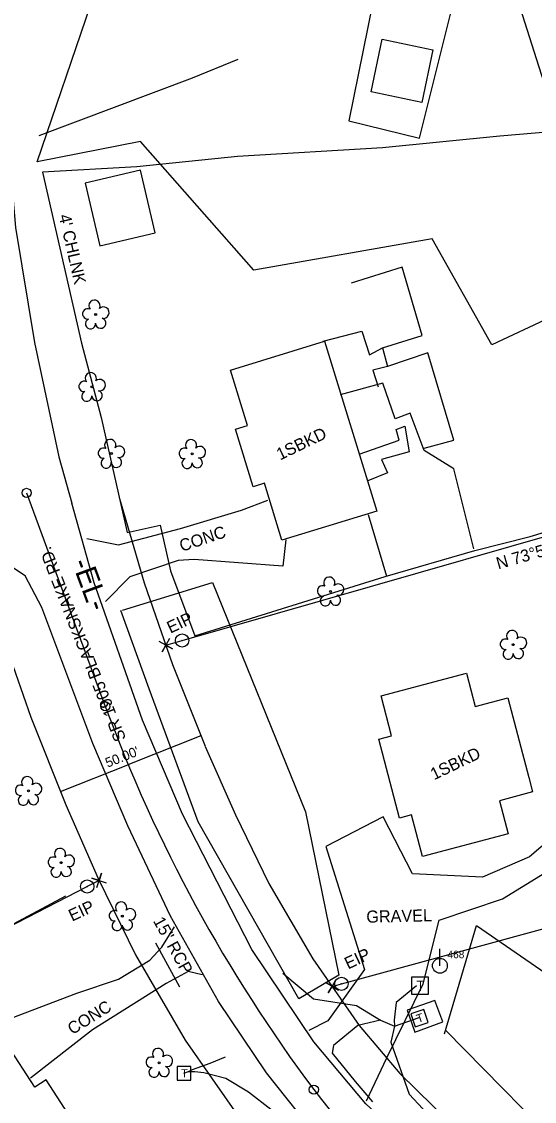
# Model space of a CAD drawing. Extents: x 1380524 to 1382335, y 594765 to 596944.
# Drawn here: x 1381171.1 to 1381340.7, y 595529.8 to 595887.1 of the extents above; entities that cross this region are included whole.
import ezdxf

# ---------------------------------------------------------------- set-up
doc = ezdxf.new("R2010")
doc.units = 0
for name, color, linetype in [('Exist Horizontal Alignment', 7, 'Continuous'), ('Exist Horizontal Alignment Direction Label', 7, 'Continuous'), ('Exist Horizontal Alignment Station Label', 7, 'Continuous'), ('Exist Other Culture Fence Line', 7, 'Continuous'), ('Exist Other Culture Fence Line Text', 7, 'Continuous'), ('Exist Roads EOP', 7, 'Continuous'), ('Exist Roads EOP Other', 7, 'Continuous'), ('Exist Structure Major Bridge WW', 7, 'Continuous'), ('Exist Structure Major Deck Tunnel Box Culvert', 7, 'Continuous'), ('Exist Structure Minor Pipes RCP 15 Inch', 7, 'Continuous'), ('Exist Structure Minor Pipes RCP 15 Inch Text', 7, 'Continuous'), ('Exist Utilities Power Tower CELL', 7, 'Continuous'), ('Exist Utilities Power Tower Text', 7, 'Continuous'), ('Exist Utilities Telephone Pedestal CELL', 7, 'Continuous'), ('Exist Utilities Telephone UG Cable', 7, 'Continuous'), ('Exist Vegetation Tree CELL', 7, 'Continuous'), ('Exist Vertical Profile Vertical Axis Label', 7, 'Continuous'), ('Prop Approach Slab', 7, 'Continuous'), ('Prop Approach Slab Hatching', 7, 'Continuous'), ('Prop Drainage Ditch Base Lines', 7, 'Continuous'), ('Prop Drainage Structure Pipe Elbow CELL', 7, 'Continuous'), ('Prop Drainage Structure Plot Symbol 50 Scale CELL', 7, 'Continuous'), ('Prop Earthen Structure Cut Ditch Special Detail Label', 7, 'Continuous'), ('Prop Earthen Structure Ditch Flow Line', 7, 'Continuous'), ('Prop Earthen Structure V Ditch Lateral Detail Label', 7, 'Continuous'), ('Prop Erosion Rip Rap At Embankment Detail CELL', 7, 'Continuous'), ('Prop Horizontal Alignment Tick Large', 7, 'Continuous'), ('Prop SS Transition Line', 7, 'Continuous')]:
    doc.layers.add(name, color=color, linetype=linetype)

# ---------------------------------------------------------------- blocks, each defined once
blk = doc.blocks.new('EXIST VEGETATION TREE')
at = {"layer": 'Prop Erosion Rip Rap At Embankment Detail CELL'}
blk.add_line((0, 0), (0, 0), dxfattribs=at)
blk.add_circle((0, 0), 0.00652, dxfattribs=at)
for centre, radius, start, end in [((-0.0077, 0.0575), 0.0371, 330.16508, 219.71335), ((-0.0521, 0.0031), 0.0345, 62.66361, 279.3457), ((0.051, 0.0118), 0.038, 257.1011, 134.19993), ((-0.0341, -0.0624), 0.0338, 111.56708, 6.23104), ((0.0335, -0.058), 0.034, 181.28216, 74.55999)]:
    blk.add_arc(centre, radius, start, end, dxfattribs=at)
blk = doc.blocks.new('EXIST UTILITIES POWER POLE')
at = {"layer": 'Exist Other Culture Fence Line'}
for q in [(0, 0.1125), (0, 0)]:
    blk.add_line((0, 0), q, dxfattribs=at)
blk.add_circle((0, 0), 0.049, dxfattribs=at)
blk = doc.blocks.new('EXIST UTILITIES TELEPHONE PEDESTAL')
at = {"layer": 'Exist Utilities Telephone Pedestal CELL'}
blk.add_line((0, 0), (0, 0), dxfattribs=at)
blk.add_lwpolyline([(-0.0545, -0.0565), (0.0574, -0.0565), (0.0574, 0.0554), (-0.0545, 0.0554), (-0.0545, -0.0565)], dxfattribs=at)
blk.add_text('T', height=0.0684, dxfattribs=at).set_placement((-0.0226, -0.0343))

msp = doc.modelspace()

# ---------------------------------------------------------------- linework, layer by layer
at = {"layer": 'Exist Horizontal Alignment'}
msp.add_line((1381172.77, 595731.19), (1381198.81, 595660.55), dxfattribs=at)
msp.add_line((1381172.77, 595731.19), (1381198.81, 595660.55), dxfattribs=at)
msp.add_line((1381172.77, 595731.19), (1381198.81, 595660.55), dxfattribs=at)
msp.add_line((1381172.77, 595731.19), (1381198.81, 595660.55), dxfattribs=at)
msp.add_line((1381172.77, 595731.19), (1381198.81, 595660.55), dxfattribs=at)
for centre, radius, start, end in [((1381667.95, 595833.49), 500, 200.235, 216.8315), ((1381667.95, 595833.49), 500, 200.235, 216.8315), ((1381667.95, 595833.49), 500, 200.235, 216.8315), ((1381667.95, 595833.49), 500, 200.235, 216.8315), ((1381427.83, 595653.65), 200, 216.8315, 254.276), ((1381427.83, 595653.65), 200, 216.8315, 254.276), ((1381427.83, 595653.65), 200, 216.8315, 254.276)]:
    msp.add_arc(centre, radius, start, end, dxfattribs=at)
at = {"layer": 'Exist Horizontal Alignment Station Label'}
for centre in [(1381172.77, 595731.19), (1381198.81, 595660.55), (1381267.75, 595533.75)]:
    msp.add_circle(centre, 1.5, dxfattribs=at)
at = {"layer": 'Exist Other Culture Fence Line'}
for q in [(1381309.44, 595580.34), (1381309.44, 595574.72)]:
    msp.add_line((1381309.44, 595574.72), q, dxfattribs=at)
msp.add_circle((1381309.44, 595574.72), 2.45, dxfattribs=at)
at = {"layer": 'Exist Roads EOP'}
for points in [[(1381203.46, 595729.3), (1381211.67, 595701.41), (1381221.04, 595674.43), (1381231.78, 595647.4)], [(1381161.15, 595696), (1381164.06, 595686.12), (1381174.18, 595656.96), (1381185.71, 595627.95), (1381196.46, 595603.62), (1381208.77, 595578.34), (1381225.25, 595550.12), (1381243.05, 595524.53), (1381259.54, 595504.93), (1381280.57, 595484.48), (1381303.91, 595467.71), (1381329.76, 595452.68), (1381358.42, 595440), (1381388.14, 595431.06), (1381418.93, 595425.53), (1381449.98, 595423.57), (1381478.51, 595424.07), (1381493.32, 595424.85)], [(1381231.86, 595647.22), (1381241.81, 595624.69), (1381252.89, 595601.94), (1381267.43, 595577.05), (1381282.78, 595554.97), (1381296.18, 595539.04), (1381312.76, 595522.92), (1381331.13, 595509.71), (1381352.52, 595497.29), (1381375.81, 595486.97), (1381399.82, 595479.76), (1381424.98, 595475.23), (1381451.15, 595473.58), (1381476.8, 595474.04), (1381490.75, 595474.77)]]:
    msp.add_lwpolyline(points, dxfattribs=at)
at = {"layer": 'Exist Roads EOP Other'}
for p, q in [((1381307.71, 595563.23), (1381298.59, 595560)), ((1381310.4, 595556.17), (1381307.71, 595563.23)), ((1381298.59, 595560), (1381301.13, 595552.79)), ((1381301.13, 595552.79), (1381310.4, 595556.17))]:
    msp.add_line(p, q, dxfattribs=at)
for points in [[(1381140.01, 595540.95), (1381160.6, 595554.74), (1381189.42, 595565.66), (1381203.19, 595570.3), (1381213.54, 595576.57), (1381217.54, 595580.83), (1381221.74, 595587.6)], [(1381230.8, 595571.69), (1381226.17, 595572.84), (1381218.93, 595568.91), (1381194.54, 595553.56), (1381174.1, 595537.5)]]:
    msp.add_lwpolyline(points, dxfattribs=at)
at = {"layer": 'Exist Structure Major Bridge WW'}
for p, q in [((1381218.83, 595680.78), (1381218.83, 595680.78)), ((1381196.75, 595602.97), (1381196.75, 595602.97)), ((1381273.78, 595567.92), (1381273.78, 595567.92))]:
    msp.add_line(p, q, dxfattribs=at)
for points in [[(1381220.05, 595682.97), (1381217.62, 595678.59), (1381218.83, 595680.78), (1381221.02, 595679.57), (1381216.65, 595681.99)], [(1381195.99, 595600.59), (1381197.51, 595605.35), (1381196.75, 595602.97), (1381194.37, 595603.73), (1381199.13, 595602.21)], [(1381275.02, 595570.09), (1381272.54, 595565.75), (1381273.78, 595567.92), (1381275.95, 595566.68), (1381271.61, 595569.16)]]:
    msp.add_lwpolyline(points, dxfattribs=at)
at = {"layer": 'Exist Structure Minor Pipes RCP 15 Inch'}
msp.add_lwpolyline([(1381215.37, 595582.28), (1381223.39, 595567.72)], dxfattribs=at)
at = {"layer": 'Exist Utilities Power Tower CELL'}
for p in [(1381230.41, 595650.85), (1381183.95, 595632.38)]:
    msp.add_line(p, (1381206.78, 595641.46), dxfattribs=at)
at = {"layer": 'Exist Utilities Power Tower Text'}
for p, q in [((1381224.21, 595682.33), (1381574.12, 595782.88)), ((1381218.83, 595680.78), (1381224.21, 595682.33)), ((1381276.88, 595568.76), (1381591.94, 595654.76)), ((1381196.75, 595602.97), (1381192.84, 595600.95)), ((1381043.39, 595523.89), (1381192.84, 595600.95)), ((1381273.78, 595567.92), (1381276.88, 595568.76))]:
    msp.add_line(p, q, dxfattribs=at)
at = {"layer": 'Exist Utilities Telephone UG Cable'}
for p, q in [((1381257.47, 595572.3), (1381267.65, 595563.77)), ((1381301.72, 595568.1), (1381294.97, 595562.52)), ((1381267.65, 595563.77), (1381281.9, 595561.53)), ((1381281.9, 595561.53), (1381289.76, 595556.78)), ((1381294.97, 595562.52), (1381294.26, 595556.78)), ((1381289.76, 595556.78), (1381282.25, 595554.99)), ((1381289.76, 595556.78), (1381294.46, 595554.79)), ((1381294.26, 595556.78), (1381294.46, 595554.79)), ((1381294.46, 595554.79), (1381302.56, 595557.56)), ((1381282.25, 595554.99), (1381274.25, 595548.31)), ((1381294.46, 595554.79), (1381293.23, 595549.44)), ((1381293.23, 595549.44), (1381299.22, 595532.27)), ((1381274.25, 595548.31), (1381273.82, 595545.81)), ((1381273.82, 595545.81), (1381281.43, 595536.44)), ((1381227.67, 595540.43), (1381233.47, 595542.5)), ((1381233.47, 595542.5), (1381238.55, 595544.55)), ((1381224.79, 595539.15), (1381226.33, 595539.73)), ((1381226.33, 595539.73), (1381227.67, 595540.43)), ((1381226.33, 595539.73), (1381228.41, 595539.77)), ((1381228.41, 595539.77), (1381231.35, 595539.38)), ((1381231.35, 595539.38), (1381238.68, 595537.51)), ((1381238.68, 595537.51), (1381246.19, 595533.02)), ((1381281.43, 595536.44), (1381287.19, 595529.71)), ((1381246.19, 595533.02), (1381253.49, 595527.28)), ((1381299.22, 595532.27), (1381308.3, 595522.57))]:
    msp.add_line(p, q, dxfattribs=at)
at = {"layer": 'Prop Drainage Ditch Base Lines'}
for points in [[(1381290.38, 595881.28), (1381307.07, 595877.81), (1381303.44, 595860.35), (1381286.75, 595863.83)], [(1381192.13, 595833.61), (1381196.98, 595812.96), (1381215.34, 595817.26), (1381210.49, 595837.91)], [(1381271.31, 595781.39), (1381288.57, 595725.12), (1381257.21, 595715.51), (1381251.43, 595734.36), (1381247.74, 595733.23), (1381241.89, 595752.3), (1381245.81, 595753.5), (1381240.18, 595771.84)], [(1381289.97, 595664.08), (1381318.21, 595671.52), (1381321.11, 595660.48), (1381331.91, 595663.32), (1381338.85, 595637), (1381340.1, 595632.23), (1381329.09, 595629.33), (1381331.98, 595618.38), (1381303.67, 595610.93), (1381300.07, 595624.61), (1381296.08, 595623.56), (1381289.2, 595649.66), (1381293.47, 595650.78)], [(1381142.98, 595533.61), (1381175.33, 595483.46), (1381198.57, 595498.46), (1381189.65, 595512.28), (1381193.58, 595514.81), (1381179.3, 595537), (1381175.5, 595534.56), (1381166.4, 595548.69)]]:
    msp.add_lwpolyline(points, close=True, dxfattribs=at)
for points in [[(1381290.46, 595779.14), (1381303.56, 595783.28), (1381297, 595805.84), (1381280.11, 595800.56)], [(1381304.2, 595745.95), (1381314.05, 595748.62), (1381305.43, 595777.56), (1381292.16, 595772.98)]]:
    msp.add_lwpolyline(points, dxfattribs=at)
at = {"layer": 'Prop Drainage Structure Pipe Elbow CELL'}
for points in [[(1381393.32, 595635.57), (1381379.8, 595638.57), (1381361.52, 595629.98), (1381339.11, 595610.77), (1381323.54, 595604.06), (1381300.42, 595605.15), (1381290.65, 595623.99), (1381271.69, 595614.21), (1381284.47, 595573.49), (1381272.43, 595556.5), (1381266.14, 595553.34)], [(1381285.22, 595530.01), (1381291.89, 595544.25), (1381303.93, 595568.7), (1381309.23, 595589.8), (1381330.17, 595596.89), (1381348.97, 595608.46), (1381366.3, 595623.3), (1381378.81, 595629.23), (1381388.44, 595626.33)]]:
    msp.add_lwpolyline(points, dxfattribs=at)
at = {"layer": 'Prop Drainage Structure Plot Symbol 50 Scale CELL'}
msp.add_line((1381285.69, 595724.07), (1381291.77, 595703.61), dxfattribs=at)
for points in [[(1381270.89, 595781.34), (1381283.67, 595784.74), (1381286.15, 595776.84), (1381290.46, 595779.14), (1381292.16, 595772.98), (1381287.22, 595771.83), (1381289.03, 595766.27)], [(1381320.67, 595712.68), (1381313.99, 595739.13), (1381304.25, 595745.2), (1381299.56, 595757.6), (1381294.64, 595755.65), (1381290.55, 595767.44), (1381276.5, 595763.64)], [(1381282.7, 595743.97), (1381295.93, 595748.64), (1381295.02, 595752.14), (1381297.88, 595753.26), (1381299.22, 595744.72), (1381290.08, 595742.24), (1381292.1, 595737.8), (1381285.66, 595735.2)]]:
    msp.add_lwpolyline(points, dxfattribs=at)
at = {"layer": 'Prop Earthen Structure Cut Ditch Special Detail Label'}
for points in [[(1381365.22, 595798.28), (1381326.61, 595780.2), (1381306.84, 595815.2), (1381247.89, 595804.83), (1381210.47, 595847.41), (1381176.29, 595840.7), (1381193.99, 595892.72), (1381228.48, 595895.26), (1381260.25, 595890.55), (1381288.84, 595901.2), (1381279.35, 595854.23), (1381302.68, 595848.54), (1381316.62, 595904.23), (1381334.31, 595896.83), (1381364.84, 595800.74)], [(1381204.52, 595692.42), (1381234.26, 595701.53), (1381265.03, 595625.65), (1381275.97, 595571.57), (1381262.79, 595563.82), (1381229.48, 595622.35), (1381213.26, 595666.34), (1381203.91, 595692.31)], [(1381311.01, 595552.25), (1381321.59, 595588.1), (1381354.11, 595565.54), (1381373.79, 595564.89), (1381382.69, 595595.08), (1381416.12, 595616.7), (1381418.47, 595677.64), (1381445.54, 595666.13), (1381483.46, 595545.08), (1381491.42, 595475.89), (1381457.51, 595475.03), (1381424.36, 595495.63), (1381355.51, 595508.44), (1381311.33, 595553.4)]]:
    msp.add_lwpolyline(points, dxfattribs=at)
at = {"layer": 'Prop Earthen Structure Ditch Flow Line'}
for points in [[(1381246.12, 596186.92), (1381252.41, 596168.85), (1381256.49, 596147.87), (1381257.46, 596126.94), (1381254.67, 596105.85), (1381249.36, 596087.97), (1381241.72, 596070.15), (1381228.75, 596046.59), (1381211.47, 596018.6), (1381194.69, 595990.16), (1381182.03, 595962.49), (1381174.06, 595937.34), (1381169.64, 595916.69), (1381167.03, 595898.25), (1381165.59, 595870.2), (1381166.09, 595853.66), (1381169.08, 595819.04), (1381175.35, 595780.97), (1381183.42, 595743.09), (1381187.72, 595727.78)], [(1381491.33, 595459.68), (1381464.85, 595458.25), (1381435.67, 595459.27), (1381408.13, 595463.04), (1381381.89, 595469.34), (1381356.9, 595478.55), (1381331.5, 595491.59), (1381306.2, 595509.27), (1381284.93, 595529.02), (1381267.78, 595549.61), (1381247.25, 595580.06), (1381224.31, 595624.91), (1381211.16, 595655.93), (1381195.13, 595701.47), (1381187.72, 595727.78)], [(1381192.71, 595716.11), (1381203.19, 595714.04), (1381223.69, 595719.4), (1381243.89, 595725.51), (1381252.5, 595728.78)], [(1381258.45, 595715.67), (1381257.48, 595706.89), (1381228.2, 595709.14), (1381222.88, 595708.78), (1381206.9, 595703.46), (1381198.9, 595695.23)], [(1381492.25, 595440), (1381464.79, 595438.13), (1381437.85, 595438.71), (1381408.74, 595442.02), (1381381.18, 595448.34), (1381355.66, 595457.45), (1381331.8, 595468.68), (1381308.83, 595482.8), (1381287.93, 595499.23), (1381269.66, 595517.22), (1381252.13, 595539.26), (1381236.19, 595562.85), (1381220.35, 595591.19), (1381206.28, 595620.98), (1381194.7, 595648.28), (1381177.83, 595693.24), (1381172.27, 595703.71), (1381163.83, 595709.25)]]:
    msp.add_lwpolyline(points, dxfattribs=at)
at = {"layer": 'Prop Earthen Structure V Ditch Lateral Detail Label'}
for points in [[(1381176.95, 595849.46), (1381227.65, 595868.51), (1381242.75, 595874.72)], [(1381392.81, 595854.66), (1381329.27, 595849.24), (1381290.43, 595845.39), (1381242.5, 595842.5), (1381209.26, 595839.07), (1381178.08, 595837.25), (1381190.93, 595780.69), (1381197.44, 595756.1), (1381206.02, 595718.03), (1381216.97, 595720.51), (1381220.39, 595705.38), (1381228.44, 595683.92), (1381291.34, 595703.48), (1381320.98, 595712.14), (1381339.23, 595716.75), (1381371.02, 595726.37), (1381419.86, 595740.72), (1381392.96, 595854.62)], [(1381069.79, 595537.28), (1381129.17, 595567.6), (1381185.79, 595597.82)]]:
    msp.add_lwpolyline(points, dxfattribs=at)
at = {"layer": 'Prop SS Transition Line'}
for centre, radius in [((1381224.21, 595682.33), 2.2), ((1381224.21, 595682.33), 0.0707), ((1381192.84, 595600.95), 2.2), ((1381192.84, 595600.95), 0.0707), ((1381276.88, 595568.76), 2.2), ((1381276.88, 595568.76), 0.0707)]:
    msp.add_circle(centre, radius, dxfattribs=at)

# ---------------------------------------------------------------- block references
at = {"layer": 'Exist Other Culture Fence Line', "xscale": 50, "yscale": 50}
msp.add_blockref('EXIST UTILITIES POWER POLE', (1381309.44, 595574.72), dxfattribs=at)
at = {"layer": 'Exist Utilities Telephone Pedestal CELL'}
for p, xscale, yscale in [((1381302.76, 595568.13), 50, 50), ((1381224.79, 595539.15), 40, 40)]:
    msp.add_blockref('EXIST UTILITIES TELEPHONE PEDESTAL', p, dxfattribs=dict(at, xscale=xscale, yscale=yscale))
at = {"layer": 'Exist Utilities Telephone Pedestal CELL', "xscale": 40, "yscale": 39.99999999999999, "rotation": 18.880737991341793}
msp.add_blockref('EXIST UTILITIES TELEPHONE PEDESTAL', (1381302.62, 595557.39), dxfattribs=at)
at = {"layer": 'Prop Erosion Rip Rap At Embankment Detail CELL', "xscale": 50, "yscale": 50}
for p in [(1381195.62, 595790.23), (1381194.4, 595766.26), (1381200.81, 595744.17), (1381227.54, 595744.07), (1381273.25, 595698.6), (1381333.7, 595680.96), (1381173.39, 595632.62), (1381184.23, 595608.84), (1381204.44, 595591.14), (1381216.62, 595542.64)]:
    msp.add_blockref('EXIST VEGETATION TREE', p, dxfattribs=at)

# ---------------------------------------------------------------- texts
at = {"layer": 'Exist Horizontal Alignment Direction Label'}
msp.add_text('-EL-', height=7, rotation=290.235, dxfattribs=at).set_placement((1381187.66, 595708.13))
at = {"layer": 'Exist Other Culture Fence Line Text'}
msp.add_text('N 73%%D58\'00" E', height=4, rotation=16.0333, dxfattribs=at).set_placement((1381328.73, 595705.83))
at = {"layer": 'Exist Structure Major Deck Tunnel Box Culvert'}
for p in [(1381220.33, 595684.59), (1381187.83, 595589.29), (1381279.07, 595573.46)]:
    msp.add_text('EIP', height=4, rotation=25.2286, dxfattribs=at).set_placement(p)
at = {"layer": 'Exist Structure Minor Pipes RCP 15 Inch Text'}
msp.add_text('15" RCP', height=4, rotation=298.8317, dxfattribs=at).set_placement((1381214.49, 595589.58))
at = {"layer": 'Exist Utilities Power Tower CELL'}
msp.add_text("50.00'", height=3.2, rotation=21.6735, dxfattribs=at).set_placement((1381199.57, 595640.23))
at = {"layer": 'Exist Vegetation Tree CELL'}
msp.add_text('468', height=2.5, dxfattribs=at).set_placement((1381311.94, 595577.22))
msp.add_text('468', height=2.5, dxfattribs=at).set_placement((1381311.94, 595577.22))
at = {"layer": 'Exist Vertical Profile Vertical Axis Label'}
for s, rotation, p in [('CONC', 18.4121, (1381224.1, 595711.65)), ('SR 1905 BLACKSNAKE RD.', 111.4727, (1381205.75, 595649.86)), ('CONC', 32.1748, (1381187.93, 595551.76))]:
    msp.add_text(s, height=4, rotation=rotation, dxfattribs=at).set_placement(p)
at = {"layer": 'Prop Approach Slab'}
for p in [(1381256.58, 595741.89), (1381307.49, 595636.07)]:
    msp.add_text('1SBKD', height=4, rotation=25.6474, dxfattribs=at).set_placement(p)
at = {"layer": 'Prop Approach Slab Hatching'}
msp.add_text("4' CHLNK", height=4, rotation=282.8061, dxfattribs=at).set_placement((1381183.39, 595822.91))
at = {"layer": 'Prop Horizontal Alignment Tick Large'}
msp.add_text('GRAVEL', height=4, rotation=1.3386, dxfattribs=at).set_placement((1381285.16, 595588.95))

doc.saveas('drawing.dxf')
